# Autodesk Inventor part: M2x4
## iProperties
Company: 한국ATC센터
Created: 2015-05
Part Number: M2x4
Document SubType Name: 모델링
Designer: KYOUNG IL JANG
Vendor: CBT Solutions
Author: KYOUNG IL JANG
Comments: 파생
